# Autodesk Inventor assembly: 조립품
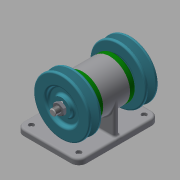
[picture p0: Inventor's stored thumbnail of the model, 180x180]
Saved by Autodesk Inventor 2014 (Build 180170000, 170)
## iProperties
Created: 2019-09
Part Number: 조립품
Document SubType Name: Assembly
Designer: kh
Author: kh
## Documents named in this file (10)
- C:\Users\kh\Desktop\490904V1025\조립품.iam
- C:\Users\kh\Desktop\490904V1025\본체.ipt
- C:\Users\kh\Desktop\490904V1025\V-벨트풀리.ipt
- C:\Users\kh\Desktop\490904V1025\너트 M10x1.ipt
- C:\Users\kh\Desktop\490904V1025\베어링 6004.ipt
- C:\Users\kh\Desktop\490904V1025\볼트 M4.ipt
- C:\Users\kh\Desktop\490904V1025\오일 실 17 30 5.ipt
- C:\Users\kh\Desktop\490904V1025\축.ipt
- C:\Users\kh\Desktop\490904V1025\커버.ipt
- C:\Users\kh\Desktop\490904V1025\키 5 x 5 x 12.ipt
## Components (2 placed, 1 different names)
1. V-벨트풀리:1 — Insert:10, Mate:7, Insert:13
2. V-벨트풀리:2 — Insert:11, Mate:8, Insert:12
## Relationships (6: Insert 4, Mate 2)
- Insert:10: V-벨트풀리:1
- Mate:7: V-벨트풀리:1
- Insert:11: V-벨트풀리:2
- Mate:8: V-벨트풀리:2
- Insert:12: V-벨트풀리:2
- Insert:13: V-벨트풀리:1
